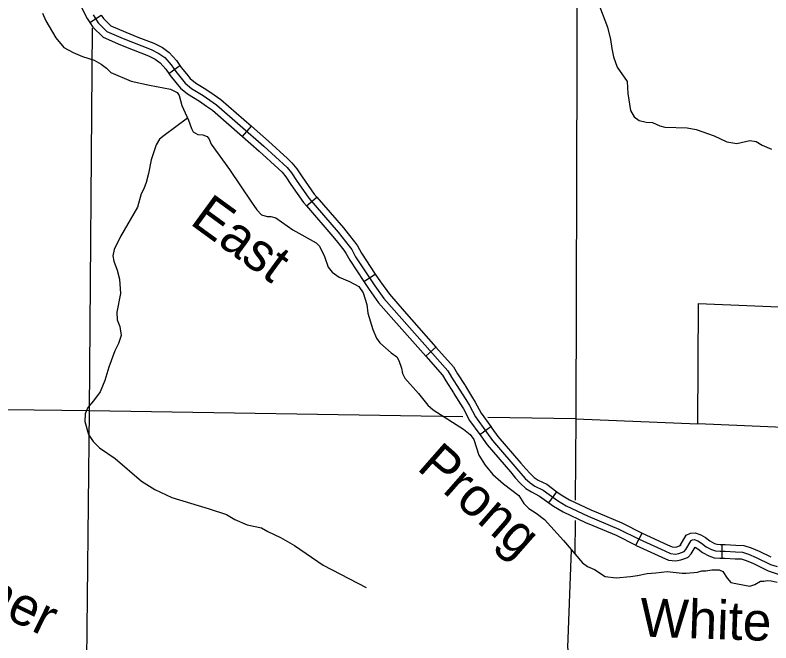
# Model space of a CAD drawing. Extents: x 0 to 3171, y 0 to 2059.
# Drawn here: x 1872.3 to 2010.8, y 363.2 to 478.3 of the extents above; entities that cross this region are included whole.
import ezdxf

# ---------------------------------------------------------------- set-up
doc = ezdxf.new("R2010")
doc.units = 0
for name, color, linetype in [('Level 35', 7, 'Continuous'), ('Level 4', 7, 'Continuous'), ('Level 45', 7, 'Continuous'), ('Level 5', 7, 'Continuous'), ('Level 8', 7, 'Continuous')]:
    doc.layers.add(name, color=color, linetype=linetype)

msp = doc.modelspace()

# ---------------------------------------------------------------- linework, layer by layer
at = {"layer": 'Level 35'}
for points in [[(1984.48, 513.02), (1983.7, 511.56), (1981.33, 507.68), (1980.86, 502.87), (1980.52, 497.61), (1980.43, 495.36), (1980.57, 492.71), (1980.64, 488.52), (1979.66, 484.81), (1979.32, 482.64), (1979.17, 480.81), (1979.52, 479.45), (1980.83, 476.04), (1981.37, 473.83), (1981.62, 472.18), (1981.95, 470.65), (1982.6, 468.76)], [(1877.28, 478.62), (1877.89, 477.21), (1879.75, 474.09), (1881.23, 472.34), (1882.93, 471.41), (1884.65, 470.69), (1886.74, 470.03), (1888.04, 469.28), (1889.04, 468.57), (1889.8, 467.76)], [(1982.6, 468.76), (1984.41, 466.13), (1984.54, 463.89), (1985.03, 460.79), (1985.7, 459.64), (1986.63, 458.94), (1987.9, 458.65), (1989.06, 458.62), (1990.4, 457.98), (1991.34, 457.73), (1995.44, 457.64), (1997.09, 457.28), (2000.37, 456.18), (2002.67, 455.07), (2004.55, 454.77), (2006.91, 455.3), (2008.08, 455.1), (2009.16, 454.44), (2010.91, 453.72)], [(1889.8, 467.76), (1893.52, 466.2), (1896.9, 465.44), (1900.76, 464.7), (1901.95, 464.1), (1902.32, 463.53), (1902.83, 461.69), (1904.04, 459.01), (1904.58, 457.5), (1904.91, 456.91), (1905.74, 456.42), (1906.67, 456.32), (1907.44, 456.04), (1907.86, 455.51), (1908.18, 454.65), (1911.53, 450), (1915.56, 443.99), (1916.57, 442.61), (1917.45, 441.69), (1918.44, 441.38), (1919.15, 441.34), (1920.04, 441.09), (1923.17, 438.93), (1927.45, 436.53), (1928.03, 435.95), (1928.96, 434.05), (1929.65, 432.08), (1930.38, 431.18), (1931.63, 430.22), (1933.56, 429.44), (1935.25, 428.52), (1936.07, 427.4), (1936.73, 425.26), (1936.89, 423.65), (1937.82, 420.68), (1938.51, 419.06), (1939.08, 418.19), (1941.17, 416.36), (1942.2, 415.67), (1942.58, 414.94), (1943.05, 413.58), (1943.26, 412.59), (1943.66, 411.71), (1946.22, 408.91), (1947.92, 406.77), (1948.9, 405.94), (1954.42, 402.36), (1955.68, 401.43), (1956.33, 400.48), (1957.27, 397.64), (1958.39, 395.8), (1959.82, 394.09), (1961.79, 392.35), (1964.59, 390.25), (1965.52, 388.78), (1966.43, 387.81), (1967.78, 387.01), (1969.28, 385.8), (1972.76, 381.95), (1976.25, 377.9), (1977.14, 377.18), (1978.46, 376.64), (1980.39, 375.36), (1982.44, 375.13), (1985.02, 375.4), (1986.31, 375.55), (1988.09, 375.95), (1989.67, 376.05), (1991.76, 376.28), (1994.52, 375.99), (1995.24, 375.97), (1997.32, 376.15)], [(1903.85, 459.4), (1899.58, 456.23), (1898.73, 455.51), (1898.15, 454.52), (1897.22, 451.78), (1896.73, 449.22), (1896.31, 447.57), (1895.87, 446.42), (1895.35, 445.53), (1894.72, 443.09), (1891.59, 437.69), (1890.45, 435.31), (1890.16, 434.15), (1890.35, 433.19), (1890.98, 431.55), (1891.41, 429.87), (1891.61, 427.26), (1890.9, 423.83), (1890.97, 422.43), (1891.48, 421.19), (1891.68, 419.55), (1891.19, 418.09), (1890.57, 416.76), (1889.45, 413.77), (1888.72, 411.32), (1887.86, 409.22), (1886.66, 407.57), (1885.62, 406.38), (1885.1, 405.22), (1885.03, 403.79), (1885.71, 401.43), (1886.6, 400.1), (1887.71, 398.99), (1890.61, 396.98), (1895.43, 392.85), (1897.9, 391.34), (1900.98, 389.87), (1907.83, 387.79), (1911.01, 386.72), (1912.56, 385.83), (1914.82, 384.84), (1917.42, 384.31), (1918.6, 383.63), (1920.91, 382.52), (1923.48, 381.08), (1928.72, 377.45), (1936.62, 373.34)], [(1974.17, 380.26), (1973.48, 362.39), (1973.78, 360.65), (1973.94, 358.94), (1973.96, 355.7), (1974.27, 354.94), (1974.3, 354.13), (1974.04, 353.07), (1974.09, 352.42), (1974.37, 351.66), (1974.47, 350.93), (1974.07, 349.27), (1974.52, 348.25), (1975.13, 347.41), (1975.55, 346.58), (1975.82, 345.47), (1975.26, 342.46)], [(1997.32, 376.15), (1998.13, 376.4), (1998.82, 376.44), (1999.93, 376.59), (2001.29, 376.58), (2001.97, 376.31), (2002.77, 375.05), (2003.44, 374.29), (2004.64, 374.03), (2006.9, 373.63), (2007.83, 373.89), (2008.85, 374.54), (2009.46, 374.54), (2010.1, 374.66), (2010.8, 374.58), (2011.92, 374.31)]]:
    msp.add_lwpolyline(points, dxfattribs=at)
at = {"layer": 'Level 4'}
msp.add_lwpolyline([(1886.39, 475.86), (1885.85, 405.77), (1885.31, 354.42)], dxfattribs=at)
at = {"layer": 'Level 45'}
for p, q in [((1885.97, 476.91), (1888.06, 478.28)), ((1900.43, 467.59), (1902.48, 469.02)), ((1913.95, 456.02), (1915.59, 457.9)), ((1925.69, 443.29), (1927.58, 444.92)), ((1936.18, 429.42), (1938.27, 430.79)), ((1947.53, 415.76), (1949.4, 417.41)), ((1957.43, 401.42), (1959.44, 402.9)), ((1970.06, 388.89), (1971.54, 390.91)), ((1986.04, 381.1), (1987.16, 383.34)), ((2001.84, 378.75), (2001.84, 381.25))]:
    msp.add_line(p, q, dxfattribs=at)
for points in [[(1881.85, 484.84), (1885.46, 477.68), (1885.97, 476.91)], [(1886.55, 478.31), (1887.51, 476.84), (1889.09, 475.29), (1892.09, 473.97), (1897.21, 471.97), (1898.61, 471.25), (1899.68, 470.49), (1900.86, 469.16), (1901.7, 467.95)], [(1888.06, 478.28), (1888.48, 477.63), (1889.8, 476.34), (1892.57, 475.13), (1894.79, 474.26)], [(1885.97, 476.91), (1886.54, 476.04), (1888.38, 474.23), (1891.61, 472.82), (1893.88, 471.93)], [(1894.79, 474.26), (1897.72, 473.11), (1899.26, 472.32), (1900.52, 471.43), (1901.84, 469.93), (1902.48, 469.02)], [(1893.88, 471.93), (1896.69, 470.83), (1897.96, 470.18), (1898.84, 469.56), (1899.87, 468.38), (1900.43, 467.59)], [(1902.48, 469.02), (1902.7, 468.69), (1903.65, 467.49), (1904.33, 466.68), (1905.3, 465.87), (1907.42, 464.61), (1908.77, 463.65)], [(1900.43, 467.59), (1900.7, 467.2), (1901.71, 465.92), (1902.55, 464.91), (1903.85, 463.82), (1906.05, 462.51), (1907.32, 461.61)], [(1901.7, 467.95), (1902.68, 466.7), (1903.44, 465.79), (1904.58, 464.85), (1906.73, 463.56), (1909.19, 461.82), (1917.85, 454.27), (1922.1, 450.37), (1922.9, 449.38), (1923.81, 447.95), (1926.11, 444.71), (1931.47, 438.51), (1933.48, 435.94), (1933.96, 435.29), (1934.66, 434), (1938.17, 428.67), (1939.87, 426.32), (1951.59, 413.05), (1952.26, 411.89), (1953.66, 409.74), (1954.84, 407.8), (1955.52, 406.71), (1956.62, 404.62), (1958.65, 401.86), (1959.78, 400.28), (1964.93, 394.26), (1965.74, 393.36), (1966.64, 392.53), (1967.53, 391.96), (1969.02, 391.2), (1971.64, 389.28), (1973.28, 388.33), (1977.29, 386.44), (1982.93, 384.06), (1986.64, 382.2), (1991.33, 380.07), (1992.35, 379.58), (1993.28, 379.49), (1993.9, 379.62), (1994.87, 379.98), (1995.18, 380.31), (1996.16, 382), (1996.38, 382.11), (1996.71, 382.13), (1997.4, 381.89), (1998.06, 381.51), (1998.93, 380.84), (1999.9, 380.31), (2000.61, 380.05), (2001.45, 380), (2002.38, 380), (2004.28, 379.89), (2005.57, 379.83), (2006.69, 379.47), (2008.09, 378.88), (2010.72, 377.58), (2011.91, 377.18)], [(1908.77, 463.65), (1909.97, 462.8), (1915.59, 457.9)], [(1907.32, 461.61), (1908.42, 460.83), (1913.95, 456.02)], [(1915.59, 457.9), (1918.69, 455.2), (1922.17, 452.01)], [(1913.95, 456.02), (1917.02, 453.34), (1920.47, 450.17)], [(1922.17, 452.01), (1923.01, 451.23), (1923.92, 450.11), (1924.85, 448.65), (1927.1, 445.48), (1927.58, 444.92)], [(1920.47, 450.17), (1921.19, 449.51), (1921.88, 448.65), (1922.77, 447.25), (1925.13, 443.94), (1925.69, 443.29)], [(1927.58, 444.92), (1932.43, 439.3), (1933.32, 438.18)], [(1925.69, 443.29), (1930.5, 437.71), (1931.35, 436.63)], [(1933.32, 438.18), (1934.48, 436.7), (1935.01, 435.96), (1935.74, 434.64), (1938.27, 430.79)], [(1931.35, 436.63), (1932.48, 435.19), (1932.9, 434.62), (1933.59, 433.36), (1936.18, 429.42)], [(1938.27, 430.79), (1939.2, 429.38), (1940.85, 427.1), (1943.58, 424.01)], [(1936.18, 429.42), (1937.14, 427.96), (1938.89, 425.54), (1941.7, 422.36)], [(1943.58, 424.01), (1949.4, 417.41)], [(1941.7, 422.36), (1947.53, 415.76)], [(1949.4, 417.41), (1952.6, 413.78), (1953.33, 412.55), (1954.72, 410.4), (1954.82, 410.24)], [(1947.53, 415.76), (1950.57, 412.31), (1951.2, 411.24), (1952.61, 409.07), (1952.68, 408.94)], [(1954.82, 410.24), (1955.9, 408.46), (1956.6, 407.33), (1957.68, 405.29), (1959.44, 402.9)], [(1952.68, 408.94), (1953.77, 407.15), (1954.43, 406.09), (1955.55, 403.96), (1957.43, 401.42)], [(1959.44, 402.9), (1959.66, 402.59), (1960.76, 401.05), (1964.95, 396.16)], [(1957.43, 401.42), (1957.64, 401.13), (1958.79, 399.51), (1963.05, 394.54)], [(1964.95, 396.16), (1965.87, 395.09), (1966.63, 394.24), (1967.41, 393.52), (1968.15, 393.05), (1969.68, 392.27), (1971.54, 390.91)], [(1963.05, 394.54), (1963.99, 393.43), (1964.85, 392.48), (1965.87, 391.53), (1966.91, 390.87), (1968.37, 390.13), (1970.06, 388.89)], [(1971.54, 390.91), (1972.32, 390.33), (1973.86, 389.44), (1977.8, 387.58), (1979.09, 387.04)], [(1970.06, 388.89), (1970.95, 388.24), (1972.7, 387.22), (1976.78, 385.3), (1978.12, 384.73)], [(1979.09, 387.04), (1983.46, 385.2), (1987.16, 383.34)], [(1978.12, 384.73), (1982.41, 382.93), (1986.04, 381.1)], [(1987.16, 383.34), (1987.18, 383.32), (1991.85, 381.2), (1992.68, 380.8), (1993.2, 380.75), (1993.55, 380.83), (1994.32, 381.11)], [(1994.16, 381.05), (1994.17, 381.06), (1995.26, 382.95), (1996.04, 383.34), (1996.89, 383.39), (1997.92, 383.03), (1998.76, 382.55), (1999.61, 381.89), (2000.42, 381.45), (2000.87, 381.28), (2001.49, 381.25), (2001.84, 381.25)], [(1986.04, 381.1), (1986.1, 381.07), (1990.8, 378.93), (1992.01, 378.36), (1993.35, 378.23), (1994.24, 378.42), (1995.17, 378.76)], [(2001.84, 381.25), (2002.42, 381.25), (2004.34, 381.14), (2005.8, 381.07), (2007.13, 380.64), (2008.61, 380.01), (2010.77, 378.95)], [(1995.17, 378.76), (1995.58, 378.91), (1996.19, 379.56), (1996.88, 380.74), (1996.88, 380.74), (1997.37, 380.46), (1998.24, 379.79), (1999.38, 379.17), (2000.35, 378.81), (2001.42, 378.75), (2001.84, 378.75)], [(2001.84, 378.75), (2002.35, 378.75), (2004.21, 378.64), (2005.35, 378.59), (2006.26, 378.3), (2007.56, 377.74), (2009.66, 376.7)], [(2009.66, 376.7), (2010.25, 376.42), (2011.53, 376), (2012.29, 375.75), (2013.87, 375.47), (2014.92, 375.3), (2016, 375), (2016.69, 374.74), (2018.02, 374.09)]]:
    msp.add_lwpolyline(points, dxfattribs=at)
at = {"layer": 'Level 5'}
for points in [[(1885.85, 405.77), (1820.35, 406.53), (1796.48, 406.89)], [(1954.33, 404.63), (1885.85, 405.77)], [(1975.04, 404.29), (1958.91, 404.55)], [(1975.04, 404.29), (1974.93, 389.38)], [(2041.57, 401.46), (1997.41, 403.34)], [(1974.91, 385.64), (1974.86, 379.5)]]:
    msp.add_lwpolyline(points, dxfattribs=at)
at = {"layer": 'Level 8'}
for points in [[(1975.3, 520.76), (1975.26, 492.07), (1975.04, 404.29), (1997.41, 403.34), (1997.5, 425.42)], [(1997.5, 425.42), (2041.75, 423.61), (2041.57, 401.46), (2063.52, 400.53), (2080.36, 399.93)]]:
    msp.add_lwpolyline(points, dxfattribs=at)

# ---------------------------------------------------------------- texts
at = {"layer": 'Level 35'}
for s, rotation, p in [('East', 323.8716, (1904.1, 440.11)), ('Prong', 318.7124, (1945.7, 395.11)), ('Abner', 333.8198, (1855.31, 375.25)), ('White', 357.9802, (1986.7, 364.4))]:
    msp.add_text(s, height=7.04, rotation=rotation, dxfattribs=at).set_placement(p)

doc.saveas('drawing.dxf')
